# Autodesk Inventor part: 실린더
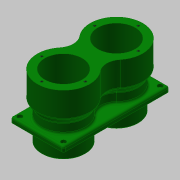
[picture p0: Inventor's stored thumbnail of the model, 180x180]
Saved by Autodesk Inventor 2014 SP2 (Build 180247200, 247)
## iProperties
Created: 2016-11
Part Number: 실린더
Material: 알루미늄 6061
Document SubType Name: Modeling
Designer: mduedu
Density: 2.71 g/cm^3
Mass: 1199.26 g
Surface Area: 1038.68 cm^2
Volume: 442.531 cm^3
Appearance: 진녹색
Author: mduedu
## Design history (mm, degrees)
sketch "스케치1"
  geometry: L1 (0, 0)-(0, 101); L2 (30, 0)-(30, 101); L3 (30, 101)-(42, 101); L4 (42, 101)-(42, 61); L5 (42, 61)-(35, 51); L6 (35, 51)-(35, 0); L7 (35, 0)-(30, 0)
  constraints: 14 end point, 4 parallel, 2 horizontal alignment, 1 perpendicular, 1 vertical
  dimensions: "d0" = 101 distance of L1.start L1.end; "d1" = 60 diameter of L2.end L1; "d2" = 84 diameter of L3.end L1; "d3" = 70 diameter of L6.end L1; "d4" = 40 distance of L3.end L4.end; "d5" = 50 vertical distance of L5.end L3.end
revolve "회전1" stored, may be unused: angle "d6" = 90 deg
node "작업 평면1"
sketch "스케치2"
  geometry: L1 (-42.5, -42.5)-(42.5, -42.5); L2 (42.5, -42.5)-(42.5, 42.5); L3 (42.5, 42.5)-(-42.5, 42.5); L4 (-42.5, 42.5)-(-42.5, -42.5); L5 (-42.5, -42.5)-(42.5, 42.5); L6 (42.5, -42.5)-(-42.5, 42.5); C1 r 35 at (0, 0) reference; C2 r 35 at (0, 0); 1 further point
  constraints: 12 end point, 2 midpoint, 2 parallel, 2 perpendicular, 1 centre point, 1 coincident, 1 concentric, 1 horizontal
  dimensions: "d8" = 85 distance of L2.end L3.end
extrude "돌출1" join sketch "스케치2" distance "d10" = 8; taper "d11" = 0 deg
chamfer "모따기1" distance "d14" = 1; stored, may be unused: second distance "d15" = 2, angle "d16" = 45 deg
chamfer "모따기2" distance "d17" = 5; stored, may be unused: second distance "d18" = 2, angle "d19" = 15 deg
sketch "스케치3"
  geometry: L1 (-35, -35)-(35, -35); L2 (35, -35)-(35, 35); L3 (35, 35)-(-35, 35); L4 (-35, 35)-(-35, -35); L5 (-35, -35)-(35, 35); L6 (35, -35)-(-35, 35); 3 further points
  constraints: 12 end point, 2 coincident, 2 midpoint, 2 parallel, 1 horizontal, 1 perpendicular
  dimensions: "d20" = 70 distance of L3.end L2.end; "d21" = 70 distance of L2.end L1.end
sketch "스케치4"
  geometry: 2 further points
  constraints: 2 other
hole "구멍1" sketch "스케치4" at (-35, 35), (35, 35) diameter "d22" = 4.5; stored, may be unused: countersink angle "d26" = 90 deg, drill point angle "d28" = 0 deg; dims "d23" = 6, "d24" = 8, "d25" = 4.6, "d27" = 8
sketch "스케치5"
  geometry: 3 further points
  constraints: 3 other
hole "구멍2" sketch "스케치5" at (35, 0), (-35, 0), (0, 35) diameter "d29" = 4.134; stored, may be unused: countersink angle "d33" = 90 deg, drill point angle "d35" = 120 deg; dims "d30" = 7.5, "d31" = 4, "d32" = 2, "d34" = 10
fillet "모깎기3" dims "d36" = 3
fillet "모깎기4" dims "d37" = 3
sketch "스케치6"
  geometry: L1 (0, 0)-(0, -85); A1 r 42 centre (0, 0) between (32.469, -26.642) and (-32.469, -26.642) reference; A2 r 42 centre (0, -85) between (32.469, -58.358) and (-32.469, -58.358) reference; A3 r 25 centre (51.795, -42.5) between (32.469, -58.358) and (32.469, -26.642); A4 r 25 centre (-51.795, -42.5) between (-32.469, -26.642) and (-32.469, -58.358); A5 r 25 centre (51.795, -42.5) between (32.469, -26.642) and (32.469, -58.358); A6 r 25 centre (-51.795, -42.5) between (-32.469, -58.358) and (-32.469, -26.642); A7 r 42 centre (0, 0) between (-32.469, -26.642) and (32.469, -26.642); A8 r 42 centre (0, -85) between (32.469, -58.358) and (-32.469, -58.358); A9 r 42 centre (0, 0) between (32.469, -26.642) and (-32.469, -26.642); A10 r 42 centre (0, -85) between (-32.469, -58.358) and (32.469, -58.358); 1 further point
  constraints: 20 point on circle, 8 centre point, 2 coincident, 2 end point, 2 tangent, 1 symmetric about line, 1 vertical, 1 other
  dimensions: "d38" = 50 diameter of A3
node "작업 평면2"
sketch "스케치7"
  geometry: A1 r 25 centre (9.795, -42.5) between (-9.531, -26.642) and (-9.531, -58.358) reference; A2 r 42 centre (-42, 0) between (-74.469, -26.642) and (-9.531, -26.642) reference; A3 r 42 centre (-42, -85) between (-9.531, -58.358) and (-74.469, -58.358) reference; A4 r 25 centre (-93.795, -42.5) between (-74.469, -58.358) and (-74.469, -26.642) reference; 1 further point
node "작업 평면3"
sketch "스케치8"
  geometry: L1 (-35, 0)-(-35, -85); A1 r 35 centre (-35, 0) between (-10.294, -24.792) and (-59.706, -24.792) reference; A2 r 35 centre (-35, -85) between (-10.294, -60.208) and (-59.706, -60.208) reference; A3 r 25 centre (7.353, -42.5) between (-10.294, -60.208) and (-10.294, -24.792); A4 r 25 centre (-77.353, -42.5) between (-59.706, -24.792) and (-59.706, -60.208); A5 r 25 centre (7.353, -42.5) between (-10.294, -24.792) and (-10.294, -60.208); A6 r 25 centre (-77.353, -42.5) between (-59.706, -60.208) and (-59.706, -24.792); A7 r 35 centre (-35, 0) between (-59.706, -24.792) and (-10.294, -24.792); A8 r 35 centre (-35, -85) between (-10.294, -60.208) and (-59.706, -60.208); 1 further point
  constraints: 16 point on circle, 6 centre point, 2 coincident, 2 end point, 2 tangent, 1 symmetric about line, 1 vertical, 1 other
  dimensions: "d40" = 50 diameter of A3
sketch "스케치9"
  geometry: A1 r 25 centre (42.353, -42.5) between (24.706, -24.792) and (24.706, -60.208) reference; A2 r 35 centre (0, 0) between (-24.706, -24.792) and (24.706, -24.792) reference; A3 r 35 centre (0, -85) between (24.706, -60.208) and (-24.706, -60.208) reference; A4 r 25 centre (-42.353, -42.5) between (-24.706, -60.208) and (-24.706, -24.792) reference; 1 further point
feature "로프트1" sketch "스케치8", "스케치9" dims "d42" = 0, "d43" = 90 deg, "d44" = 0, "d45" = 90 deg
feature "로프트2" dims "d46" = 0, "d47" = 90 deg, "d48" = 0, "d49" = 90 deg
  node "모서리1"
feature "로프트3" dims "d50" = 0, "d51" = 90 deg, "d52" = 0, "d53" = 90 deg
  node "모서리2"
fillet "모깎기5" dims "d54" = 3
node "솔리드1"
mirror "대칭1"
other parameters: "d7" = -27
